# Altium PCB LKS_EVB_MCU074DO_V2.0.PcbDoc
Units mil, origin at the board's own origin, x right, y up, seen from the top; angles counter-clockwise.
Board outline 2625 x 1560 mil, 2 copper layers (Top Layer, Bottom Layer); 38 components, 55 nets, 182 pads, 64 vias.
Unrouted connection lines stored in the file: 4.
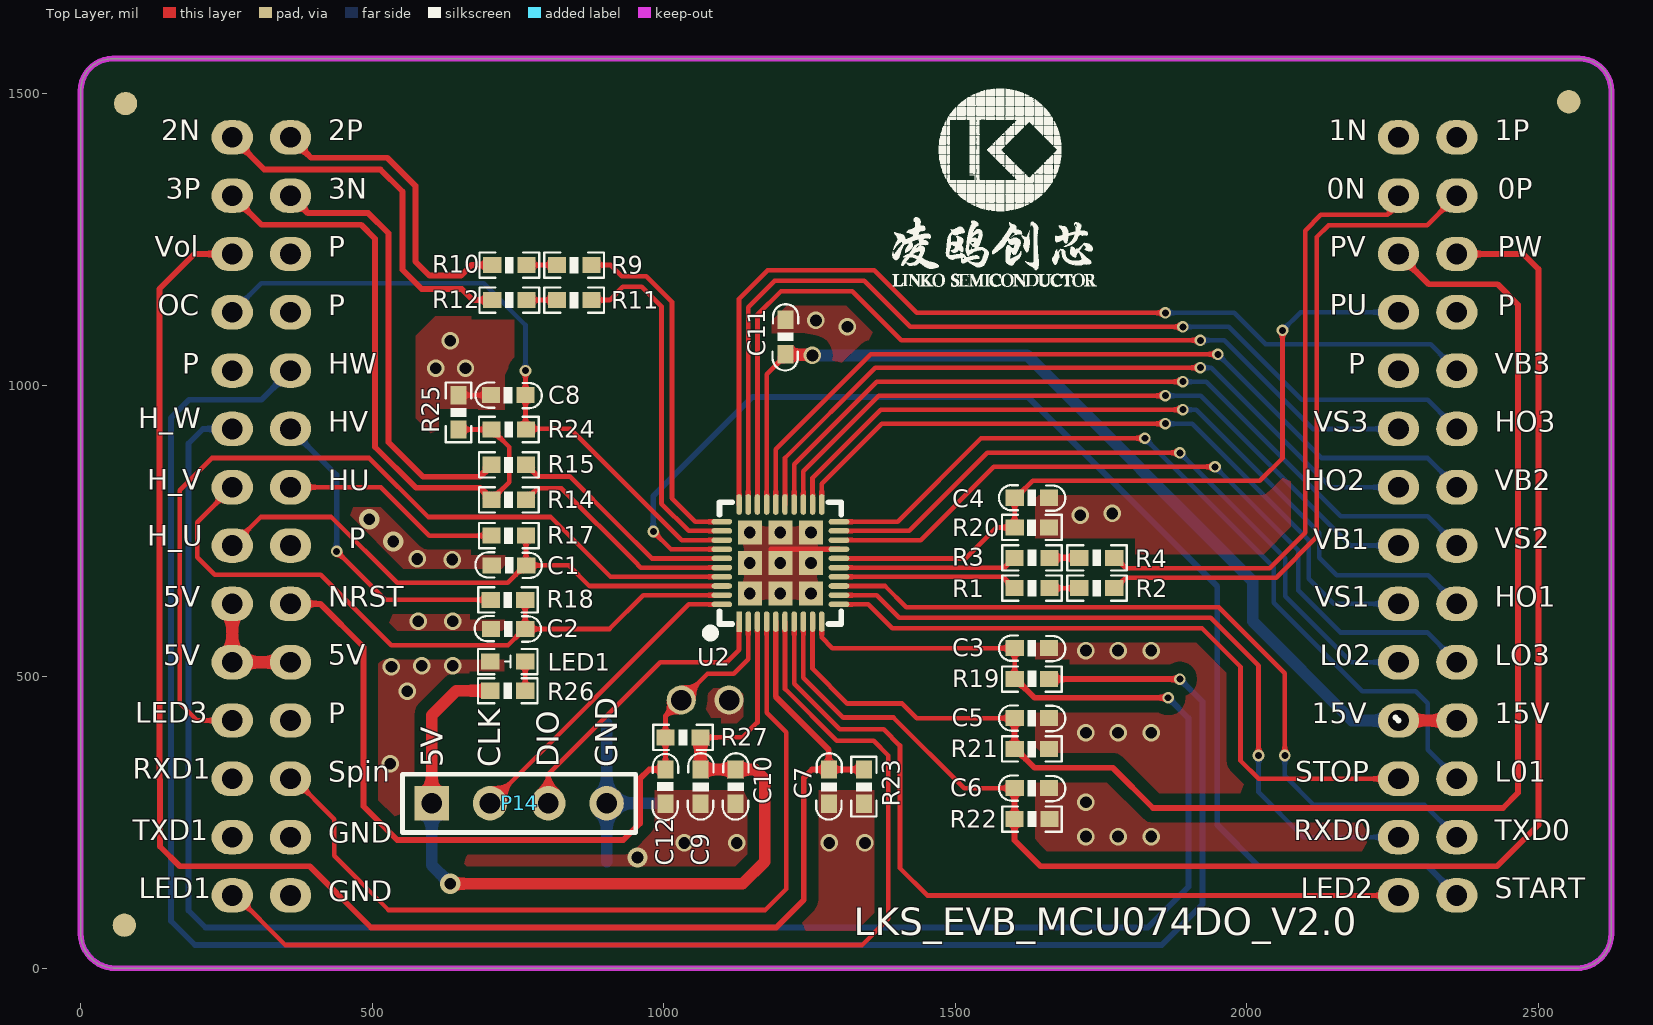
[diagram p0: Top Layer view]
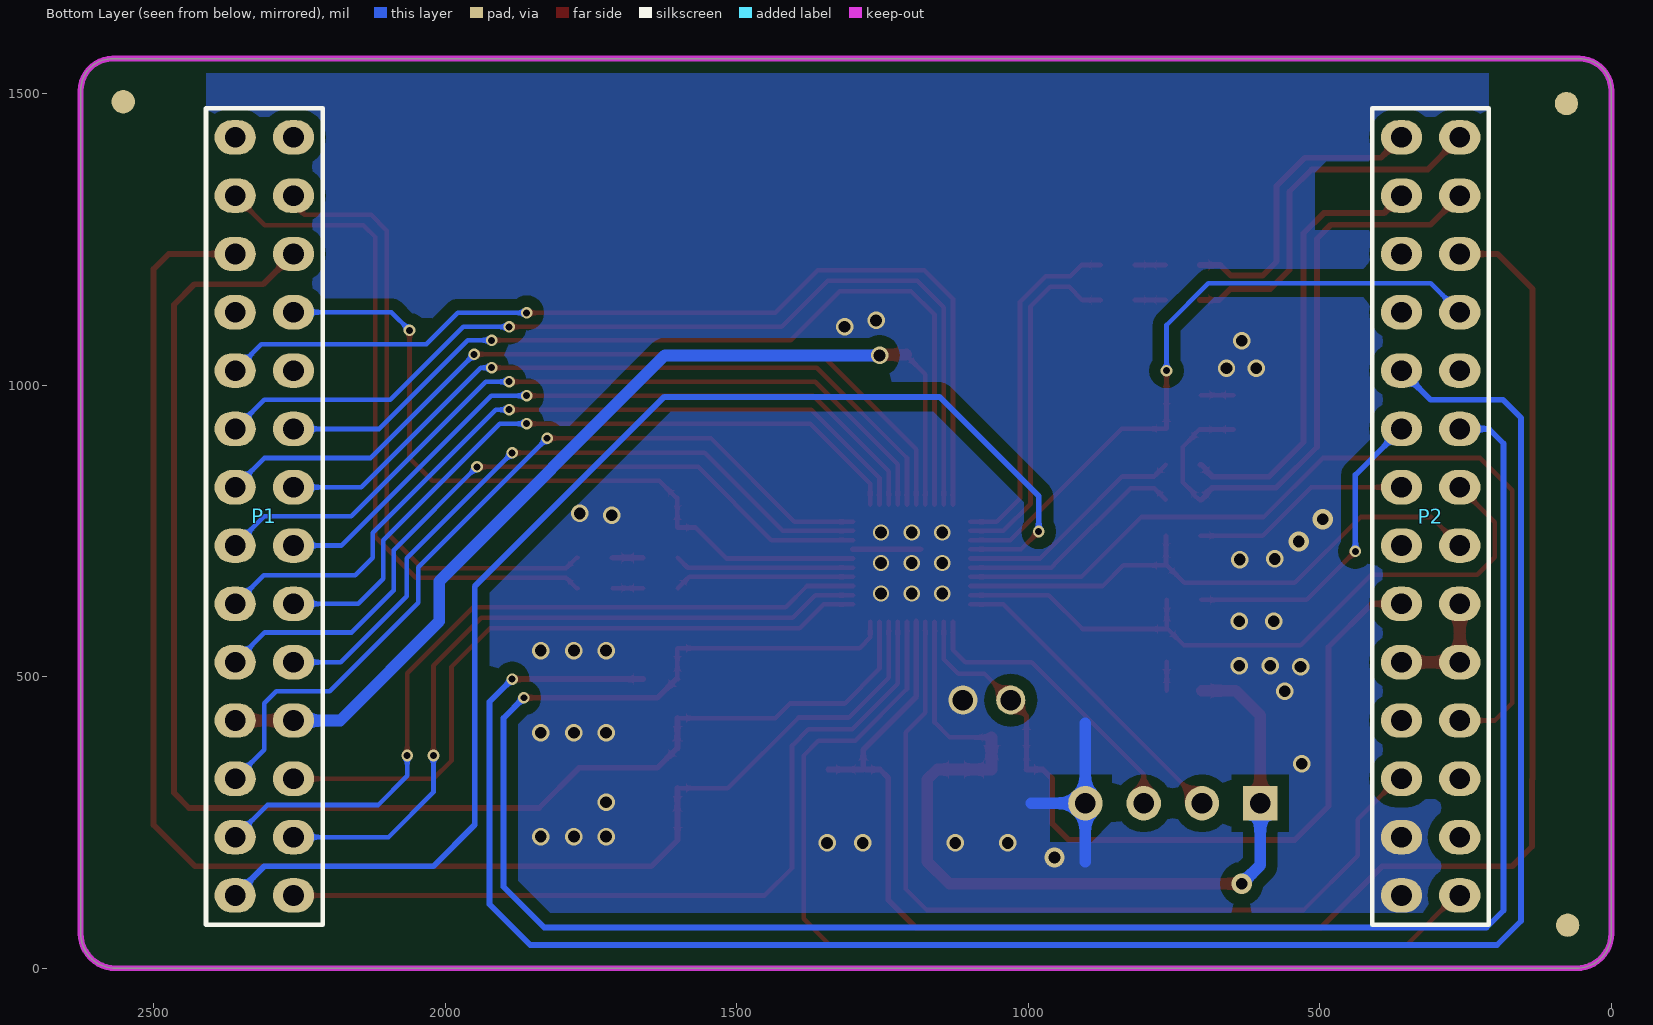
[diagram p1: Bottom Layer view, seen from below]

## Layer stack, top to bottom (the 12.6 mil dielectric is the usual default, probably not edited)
Top Solder: solder mask 0.4, Solder Resist, Dk 3.5
Top Layer: signal copper 1.4
Dielectric1: dielectric 12.6, FR-4, Dk 4.8
Bottom Layer: signal copper 1.4
Bottom Solder: solder mask 0.4, Solder Resist, Dk 3.5

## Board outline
0,60 ccw(c60,60) 60,0 2565,0 ccw(c2565,60) 2625,60 2625,1505 ccw(c2570,1505) 2570,1560 55,1560 ccw(c55,1505) 0,1505

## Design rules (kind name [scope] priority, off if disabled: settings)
Clearance Clearance_1 [InPolygon] p1: gap=20 ignorepadtopadclearanceinfootprint=FALSE except(0: Arc-Hole Track-Hole SMDPad-Hole THPad-Hole Via-Hole Fill-Hole Poly-Hole Region-Hole Text-Hole)
Clearance [All] p2: gap=0 ignorepadtopadclearanceinfootprint=FALSE
ComponentClearance [All] p1: gap=0 collisioncheckmode=3 verticalgap=0 showdistances=FALSE
FabricationTestpoint [(IsPad And (OnTopLayer Or OnBottomLayer))] p1: side=3 testpointundercomponent=TRUE minsize=40 maxsize=100 preferedsize=60 minholesize=0 maxholesize=40 preferedholesize=32 testpointgrid=1 allowsidetop=TRUE allowsidebottom=TRUE usegrid=TRUE gridtolerance=0.01
HoleSize [All] p1: absolutevalues=TRUE maxlimit=100 minlimit=0 maxpercent=80.000 minpercent=20.000
PolygonConnect [All] p1: connectstyle=Direct reliefconductorwidth=25 reliefentries=4 polygonreliefangle="90 Angle" airgapwidth=10
RoutingVias [All] p1: holewidth=28 width=50 viastyle="Through Hole" minholewidth=0 minwidth=8 maxholewidth=28 maxwidth=50
SilkToSolderMaskClearance SilkscreenOverComponentPads [IsPad] p1: minsilkscreentomaskgap=10 clearancetoexposedcopper=TRUE
SolderMaskExpansion [All] p1: expansion=4 istentingtop=FALSE
Width [All] p1: maxlimit=100 minlimit=2 preferedwidth=10
26 further rules are at their usual default settings.

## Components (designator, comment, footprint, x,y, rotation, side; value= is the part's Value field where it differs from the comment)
C1 "10nF/16V" 0603C 764.06,691 r180 top
C2 "10nF/16V" 0603C 762.71,581.86 r180 top
C3 "10nF/16V" 0603C 1601.65,549 r0 top
C4 "1nF/16V" 0603C 1601.65,807 r0 top
C5 "1nF/16V" 0603C 1601.65,429.21 r0 top
C6 "1nF/16V" 0603C 1601.65,309 r0 top
C7 "100nF/50V" 0603C 1283,281.94 r90 top
C8 "1nF/50V" 0603C 703.82,983 r0 top
C9 "10uF/16V" 0603C 1063,281.94 r90 top
C10 "100nF/50V" 0603C 1123,281.94 r90 top
C11 "4.7uF/25V" 0603C 1209,1112.23 r270 top
C12 "100nF/50V" 0603C 1003,341 r270 top
LED1 "LED" "LED 0603R" 732.5,526 r180 top
P1 "Header 14X2A" "HDR 2X14 底层" 2260,1425 r180 bottom
P2 "Header 14X2A" "HDR 2X14 底层" 260,1425 r180 bottom locked
P14 "Header 4" HDR1X4 602,283 r0 top
R1 "20K1%" 0603R#1 1631.36,652 r180 top value=K
R2 "20K1%" 0603R#1 1742.71,652 r180 top value=K
R3 "20K1%" 0603R#1 1631.36,704 r180 top value=K
R4 "20K1%" 0603R#1 1742.71,704 r180 top value=K
R9 "20K1%" 0603R#2 816.94,1206 r0 top value=K
R10 "20K1%" 0603R#2 705.65,1206 r0 top value=K
R11 "20K1%" 0603R#2 816.94,1146 r0 top value=K
R12 "20K1%" 0603R#2 705.65,1146 r0 top value=K
R14 "1K1%" 0603R#2 704.65,803.5 r0 top value=K
R15 "1K1%" 0603R#2 704.65,863.5 r0 top value=K
R17 "2K" 0603R#2 704.65,741.9 r0 top value=K
R18 "2K" 0603R#2 703.3,631.86 r0 top value=K
R19 "2K" 0603R#2 1660.71,496 r180 top value=K
R20 "1K" 0603R#2 1601.65,756 r0 top value=K
R21 "1K" 0603R#2 1601.65,376.21 r0 top value=K
R22 "1K" 0603R#1 1631.36,256 r0 top value=K
R23 "1K1%" 0603R#2 1343,282 r90 top value=K
R24 "1K1%" 0603R#2 763.71,924 r180 top value=K
R25 "10R" 0603R#2 648,923.94 r90 top value=K
R26 "330R" 0603R#1 732.5,476 r180 top value=330
R27 "20K" 0603R#1 1033,396 r0 top value=K
U2 "LKS32MC074DOF8Q8" QFN40 1200,695 r90 top

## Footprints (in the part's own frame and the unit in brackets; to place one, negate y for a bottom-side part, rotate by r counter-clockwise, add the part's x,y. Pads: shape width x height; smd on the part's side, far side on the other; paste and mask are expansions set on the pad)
0603C [mm]
  rect 0.8x0.7 smd: 1(0,0) 2(1.5,0)
  silkscreen extent -0.68,-0.57 2.21,0.55
0603R#1 [mm] "电阻"
  rect 0.8x0.7 smd: 1(-0.762,0) 2(0.762,0)
  silkscreen extent -1.3,-0.55 1.3,0.55, body extent -0.8,-0.4 0.8,0.4, height 0.45
0603R#2 [mm]
  rect 0.8x0.7 smd: 1(0,0) 2(1.5,0)
  silkscreen extent -0.55,-0.55 2.05,0.55
HDR1X4 [mm] "Connector; Header; 4 Position"
  rect 1.5x1.5 hole 0.9: 1(0,0)
  round 1.5 hole 0.9: 2(2.54,0) 3(5.08,0) 4(7.62,0)
  silkscreen extent -1.27,-1.27 8.89,1.27
"HDR 2X14 底层" [mm] "双排针 2.54mm 底层"
  oval 1.8x1.5 hole 0.9: 1(0,0) 2(0,-2.54) 3(0,-5.08) 4(0,-7.62) 5(0,-10.16) 6(0,-12.7) 7(0,-15.24) 8(0,-17.78) 9(0,-20.32) 10(0,-22.86) 11(0,-25.4) 12(0,-27.94) 13(0,-30.48) 14(0,-33.02) 15(-2.54,0) 16(-2.54,-2.54) 17(-2.54,-5.08) 18(-2.54,-7.62) 19(-2.54,-10.16) 20(-2.54,-12.7) 21(-2.54,-15.24) 22(-2.54,-17.78) 23(-2.54,-20.32) 24(-2.54,-22.86) 25(-2.54,-25.4) 26(-2.54,-27.94) 27(-2.54,-30.48) 28(-2.54,-33.02)
  silkscreen extent -3.81,-34.29 1.27,1.27, body extent -3.81,-34.29 1.27,1.27, height 8.5
"LED 0603R" [mm] "LED"
  rect 0.8x0.7 smd: 1(-0.762,0) 2(0.762,0)
  silkscreen extent -1.3,-0.55 1.3,0.55, body extent -0.8,-0.4 0.8,0.4, height 0.47
QFN40 [mm] "LINKO-084D"
  rect 1.05x1.05 smd: 0(-1.33,-1.33) 0(-1.33,0) 0(-1.33,1.33) 0(0,1.33) 0(0,0) 0(0,-1.33) 0(1.33,-1.33) 0(1.33,0) 0(1.33,1.33)
  rect 0.9x0.24 smd: 1(-2.55,1.8)
  oval 0.9x0.24 smd: 2(-2.55,1.4) 3(-2.55,1) 4(-2.55,0.6) 5(-2.55,0.2) 6(-2.55,-0.2) 7(-2.55,-0.6) 8(-2.55,-1) 9(-2.55,-1.4) 10(-2.55,-1.8) 21(2.55,-1.8) 22(2.55,-1.4) 23(2.55,-1) 24(2.55,-0.6) 25(2.55,-0.2) 26(2.55,0.2) 27(2.55,0.6) 28(2.55,1) 29(2.55,1.4) 30(2.55,1.8)
  oval 0.24x0.9 smd: 11(-1.8,-2.55) 12(-1.4,-2.55) 13(-1,-2.55) 14(-0.6,-2.55) 15(-0.2,-2.55) 16(0.2,-2.55) 17(0.6,-2.55) 18(1,-2.55) 19(1.4,-2.55) 20(1.8,-2.55) 31(1.8,2.55) 32(1.4,2.55) 33(1,2.55) 34(0.6,2.55) 35(0.2,2.55) 36(-0.2,2.55) 37(-0.6,2.55) 38(-1,2.55) 39(-1.4,2.55) 40(-1.8,2.55)
  silkscreen extent -3.16,-2.65 2.65,3.16, body extent -3,-3 3,3, height 0.9

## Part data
C1 C2 C3 C4 C5 C6: library part CAP, "Capacitor"
C7 C8 C9 C10 C11 C12: library part C, "Capacitor"
LED1: "LED_Light"
P1 P2: "Header, 14-Pin, Dual row"
P14: "Header, 4-Pin"
R1 R2 R3 R4 R9 R10 R11 R12 R14 R15 R17 R18 R19 R20 R21 R22 R23 R24 R25 R26 R27: library part Res, "Resistor"
U2: "凌鸥创芯，芯片，96M，64kK-Flash，12K-RAM,Built-in 6N Gate Drive+ldo5v"

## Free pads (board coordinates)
  round 50 hole 35: 0(1112,460) 1(1030,460)
  round 40 all layers, no hole: 3(2552,1486) 5(75,74) 5(77,1483)

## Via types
v1: diameter 30, hole 20, Top Layer to Bottom Layer, 31 vias
v2: diameter 20, hole 12, Top Layer to Bottom Layer, 20 vias
v3: diameter 28, hole 20, Top Layer to Bottom Layer, 9 vias
v4: diameter 35, hole 20, Top Layer to Bottom Layer, 4 vias

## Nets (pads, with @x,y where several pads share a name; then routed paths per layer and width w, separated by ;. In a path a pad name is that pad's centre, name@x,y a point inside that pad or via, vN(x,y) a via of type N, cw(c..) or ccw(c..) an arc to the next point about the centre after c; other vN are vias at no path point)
5V: P2.9 P2.10 P2.24 | length 200
  Top Layer w20: P2.9 P2.10 P2.24
+5V: C9.2 C10.2 P14.1 R26.2 R27.2 U2.3 | length 1569.1
  Top Layer w8: R27.2 1135,396 1160.63,421.63 U2.3
  Top Layer w20: P14.1 602,434 644,476 R26.2 ; v4(634.06,145) 1135,145 1173,183 1173,324 1156,341 C10.2 C9.2 R27.2
  Bottom Layer w20: P14.1 602,177.06 v4(634.06,145)
+15V: C11.2 P1.11 P1.25 U2.27 | length 1722.9
  Top Layer w8: U2.27 1176.38,1018.58 1209,1051.2 C11.2
  Top Layer w20: C11.2 1210.09,1052.09 1253.91,1052.09 v1(1255,1051) ; P1.11 P1.25
  Bottom Layer w20: v1(1255,1051) 1623,1051 2010,664 2010,595 2180,425 P1.11
GND: C1.2 C2.2 C3.2 C4.2 C5.2 C6.2 C7.1 C8.1 C9.1 C10.1 C11.1 C12.2 LED1.2 P2.16 P2.27 P2.28 P14.4 pad.0 R15.1 R20.2 R21.2 R22.2 R23.1 R25.2 U2.0 U2.17 | length 1265.5
  Top Layer w8: R25.2 C8.1
  Top Layer w10: P2.16 390,1295 493.28,1295 527.87,1260.4 527.87,902.13 587,843 684.39,843 693.91,852.51 693.91,854.72 702.69,863.5 R15.1@704.89,863.5 ; 1185,718.62 U2.17 ; U2.0@1200,695 v3(1200,695.11)
  Bottom Layer w20: 902,183 P14.4 ; 902,420 P14.4 ; 995,283 P14.4
  other v1: 1035,215 1125,215 1284,215 1345,215 1724,226 1779,226 1836,226 1724,285 531,351 1724,404 1779,404 1836,404 560,475 533,517 585,519 638,519 1724,545 1779,545 1836,545 579,595 638,595 637,701 577,702 1714,777 1769,780 609,1029 660,1029 634,1076 1315,1100 1261,1111
  other v3: 1147.64,642.64 1200,642.64 1252.36,642.64 1147.64,695 1252.36,695 1147.64,747.36 1200,747.36 1252.36,747.36
  other v4: 955,190 536,732 495,770
HALL_U: C1.1 P2.8 R17.2 U2.38 | length 984.8
  Top Layer w8: P2.8 309,774 430,774 543,661 732.09,661 762.09,691 C1.1 ; R17.2 763.71,691.35 C1.1 ; U2.38 872.37,655.63 837,691 C1.1
HALL_V: C2.1 P2.7 R18.2 U2.39 | length 1192.7
  Top Layer w8: P2.7 200,765 200,705 230,675 412,675 533,554 732.88,554 760.74,581.86 C2.1 ; R18.2 762.36,582.2 C2.1 ; U2.39 964.88,639.88 906.86,581.86 C2.1
HALL_W: C3.1 P2.6 R19.2 U2.10 | length 3676.5
  Top Layer w8: U2.10 1270.87,567.37 1289.24,549 C3.1 1601.65,497 R19.2@1600.65,496 ; R19.2 R19.2@1603.62,496
  Top Layer w10: R19.2@1603.62,496 1635.62,464 v2(1865,464)
  Bottom Layer w10: P2.6 210,925 185,900 185,99 214,70 1830,70 1900,140 1900,429 v2(1865,464)
HO1: P1.23 U2.22 | length 1362.1
  Top Layer w8: U2.22 1255.12,841.12 1372,958 v2(1890,958)
  Bottom Layer w8: v2(1890,958) 1913,958 2124,747 2124,704 2154,674 2311,674 P1.23
HO2: P1.7 U2.25 | length 1280.9
  Top Layer w8: U2.25 1207.87,875.1 1362.77,1030 v2(1920,1030)
  Bottom Layer w8: v2(1920,1030) 1939,1030 2144,825 P1.7
HO3: P1.20 U2.29 | length 1677.5
  Top Layer w8: U2.29 1144.88,1133.88 1190,1179 1344,1179 1423,1100 v2(1890,1100)
  Bottom Layer w8: v2(1890,1100) 1969,1100 2094,975 2310,975 P1.20
HU: P2.21 R17.1 | length 379.1
  Top Layer w8: P2.21 515,825 598.1,741.9 R17.1
HV: P2.20 R18.1 | length 541.5
  Top Layer w8: v2(439,715) 522.14,631.86 R18.1
  Bottom Layer w9.45: P2.20 439,846 v2(439,715)
HW: P2.19 R19.1 | length 3543
  Top Layer w10: R19.1 v2(1885,496)
  Bottom Layer w10: P2.19 310,975 186,975 155,944 155,81 196,40 1854,40 1924,110 1924,457 v2(1885,496)
LED1: P2.14 U2.6 | length 1798.7
  Top Layer w8: P2.14 265.91,125 350.91,40 1340,40 1385,85 1385,175 1385,365 1360,390 1297,390 1207.87,479.13 U2.6
LED2: P1.14 U2.7 | length 1416.1
  Top Layer w8: U2.7 1223.62,488.38 1302,410 1377,410 1405,382 1405,172 1452,125 P1.14
LED3: P2.11 U2.37 | length 1504.2
  Top Layer w8: P2.11 200,425 170,455 170,820 225,875 495.11,875 596.11,774 806,774 908.62,671.38 U2.37
LO1: P1.26 U2.20 | length 1443.1
  Top Layer w8: U2.20 1400.87,765.87 1544,909 v2(1825,909)
  Bottom Layer w8: v2(1825,909) 2046,688 2046,627 2198,475 2289.5,475 2310,454.5 2310,375 P1.26
LO2: P1.10 U2.19 | length 1201.8
  Top Layer w8: U2.19 1421.12,750.12 1555,884 v2(1885,884)
  Bottom Layer w8: v2(1885,884) 2066,703 2066,638 2179,525 P1.10
LO3: P1.24 U2.18 | length 1291
  Top Layer w8: U2.18 1440.37,734.37 1566,860 v2(1945.31,860)
  Bottom Layer w8: v2(1945.31,860) 2088,717.31 2088,648 2160,576 2309,576 P1.24
NetLED1_1: LED1.1 R26.1 | length 50
  Top Layer w8: R26.1 LED1.1
NetR1_1: R1.1 R2.2 | length 52
  Top Layer w8: R1.1@1660.71,652 R2.2
NetR3_1: R3.1 R4.2 | length 51.7
  Top Layer w10: R3.1@1661,704 R4.2
NetR9_1: R9.1 R10.2 | length 52.2
  Top Layer w8: R10.2 R9.1
NetR11_1: R11.1 R12.2 | length 52.2
  Top Layer w8: R12.2 R11.1
NRST: C12.1 P2.23 pad.1 R27.1 U2.2 | length 1404.3
  Top Layer w8: C12.1 R27.1 1003,433 pad.1 1075,505 1120,505 1144.88,529.88 U2.2
  Top Layer w10: P2.23 411,625 485,551 485,278 543,220 930.5,220 959,248.5 959,325 975,341 C12.1
OC: C8.2 P2.4 R24.1 U2.33 | length 1147.1
  Top Layer w8: v2(762.87,1024.87) C8.2 762.87,925.18 839.82,925.18 1030.63,734.37 U2.33
  Bottom Layer w8: P2.4 310,1175 691,1175 762.87,1103.13 v2(762.87,1024.87)
OPA0_IN: R3.2 U2.15 | length 307.6
  Top Layer w8: U2.15 1584.13,687.13 R3.2@1601,704
OPA0_IP: R1.2 U2.14 | length 308.3
  Top Layer w8: U2.14 1581.33,671.38 R1.2@1600.71,652
OPA2_IN: R11.2 U2.32 | length 605.6
  Top Layer w8: R11.2@876.65,1145.35 R11.2 907,1146 930,1169 962,1169 996,1135 996,797 1042.88,750.12 U2.32
OPA2_IP: R9.2 U2.31 | length 603.3
  Top Layer w8: R9.2 909,1206 928,1187 970,1187 1014,1143 1014,806 1054.13,765.87 U2.31
OPA3_IN: R15.2 U2.35 | length 402.2
  Top Layer w8: R15.2@763.95,863.5 783.95,843.5 838.5,843.5 920,762 979.13,702.87 U2.35
OPA3_IP: R14.2 U2.36 | length 400.4
  Top Layer w8: R14.2@763.95,803.5 783.95,823.5 824.5,823.5 950,698 960.87,687.13 U2.36
PGND: P1.1 P1.2 P2.1 P2.2 R4.1 R12.1 R14.1 R24.2 R25.1 | length 2786.8
  Top Layer w8: R25.1 704.94,923.94 705,924 706.97,924 716.75,914.22 716.75,912.25 735,894 735,833.61 716.64,815.25 716.64,813.28 706.86,803.5 R14.1@704.89,803.5 ; R4.1 1774.68,704 1792.68,686 2039,686 2100,747 2100,1265 2127,1292 2241,1292 2260,1311 P1.2
  Top Layer w10: P2.2 310,1275 481,1275 505,1251 505,894 575,824 684.39,824 693.91,814.49 693.91,812.28 702.69,803.5 R14.1@704.89,803.5 ; P2.1 315,1370 514,1370 552,1332 552,1198 585,1165 653.55,1165 672.55,1146 R12.1
PU: C4.1 P1.4 R20.1 U2.16 | length 1292.6
  Top Layer w8: U2.16 1517.87,702.87 1571,756 R20.1 C4.1 1603.62,807 1632.62,836 2022,836 2061,875 v2(2061,1094)
  Bottom Layer w8: v2(2061,1094) 2092,1125 P1.4
PV: C5.1 P1.3 R21.1 U2.9 | length 2508.8
  Top Layer w8: U2.9 1255.12,513.88 1315,454 1409.05,454 1434.05,429 1601.44,429 C5.1 ; R21.1 R21.1@1603.62,376.21
  Top Layer w10: R21.1@1601.65,377 C5.1 ; R21.1@1603.62,376.21 1635.84,344 1770,344 1839,275 2439,275 2465,301 2465,1138 2430,1173 2312,1173 P1.3
PW: C6.1 P1.17 R22.1 U2.8 | length 2676.6
  Top Layer w8: U2.8 1239.37,498.63 1308,430 1394,430 1515,309 C6.1
  Top Layer w10: C6.1 1601.65,256.29 R22.1 1601.36,219.64 1646,175 2429,175 2500,246 2500,1199 2474,1225 P1.17
RXD0: P1.13 U2.12 | length 1258.6
  Top Layer w8: U2.12 1365.12,639.88 1404,601 1938,601 2020,519 v2(2020,365)
  Bottom Layer w8: v2(2020,365) 2020,302 2097,225 P1.13
RXD1: P2.12
SPIN: P2.26 U2.4 | length 1467.5
  Top Layer w8: P2.26 365.91,325 435,255.91 435,193 528,100 1174,100 1210,136 1210,405 1176.38,438.62 U2.4
START1: P1.28 U2.34 | length 2233.3
  Top Layer w8: v2(982,749) 1012.38,718.62 U2.34
  Bottom Layer w10: v2(982,749) 982,810 1152,980 1624,980 1949,655 1949,246 2020,175 2310,175 P1.28
STOP1: P1.12 U2.11 | length 1177.8
  Top Layer w8: U2.11 1350.87,624.13 1392,583 1923,583 1989,517 1989,356 2020,325 P1.12
SWCLK: P14.2 U2.40 | length 538.9
  Top Layer w8: P14.2 1043.13,624.13 U2.40
SWDIO: P14.3 U2.1 | length 513.9
  Top Layer w8: P14.3 802,333 994,525 1108,525 1129.13,546.13 U2.1
TXD0: P1.27 U2.13 | length 1341.1
  Top Layer w8: U2.13 1379.37,655.63 1416,619 1952,619 2065,506 v2(2065,365)
  Bottom Layer w8: v2(2065,365) 2065,330 2115,280 2305,280 P1.27
TXD1: P2.13
UP-: P2.15 R10.1 | length 527.4
  Top Layer w10: P2.15 395,1390 526,1390 574,1342 574,1212 598,1188 652.52,1188 670.52,1206 R10.1
VB1: P1.8 U2.23 | length 1237.8
  Top Layer w8: U2.23 1239.37,852.37 1369,982 v2(1860,982)
  Bottom Layer w8: v2(1860,982) 1921,982 2178,725 P1.8
VB2: P1.21 U2.26 | length 1424.5
  Top Layer w8: U2.26 1192.13,890.13 1355,1053 v2(1950,1053)
  Bottom Layer w8: v2(1950,1053) 2128,875 2310,875 P1.21
VB3: P1.19 U2.30 | length 1675.1
  Top Layer w8: U2.30 1129.13,1148.13 1178,1197 1361,1197 1434,1124 v2(1860,1124)
  Bottom Layer w8: v2(1860,1124) 1978,1124 2032,1070 2315,1070 P1.19
VOL_ADC: C7.2 P2.3 R23.2 U2.5 | length 2892.4
  Top Layer w10: P2.3 195,1225 135,1165 135,325 136,324 136,209 170,175 393,175 498,70 1193,70 1240,117 1240,327 1254,341 C7.2@1278,341 ; U2.5 1192.13,465.87 1283,375 C7.2 1342.94,341 R23.2
VP-: P1.15
VS1: P1.9 U2.21 | length 1234
  Top Layer w8: U2.21 1270.87,830.87 1374,934 v2(1860,934)
  Bottom Layer w8: v2(1860,934) 1906,934 2106.13,733.87 2106.13,667.87 2149,625 P1.9
VS2: P1.22 U2.24 | length 1380.6
  Top Layer w8: U2.24 1223.62,864.62 1365,1006 v2(1890,1006)
  Bottom Layer w8: v2(1890,1006) 1930,1006 2161,775 2310,775 P1.22
VS3: P1.6 U2.28 | length 1539.1
  Top Layer w8: U2.28 1160.63,1120.63 1201,1161 1323,1161 1407,1077 v2(1920.25,1077)
  Bottom Layer w8: v2(1920.25,1077) 1961,1077 2113,925 P1.6
WP-: P1.16 R2.1 | length 1167.2
  Top Layer w8: R2.1 1774.68,652 1792.68,670 2050,670 2120,740 2120,1254.13 2140,1274.13 2309.13,1274.13 P1.16
pads on no net: P1.5 P1.18 P2.5 P2.17 P2.18 P2.22 P2.25

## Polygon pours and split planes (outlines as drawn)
GND on Bottom Layer "Bottom Layer-No Net 1" (solid, remove dead copper, pour order 9): 210,1560 2410,1560 2410,-2 210,-2
GND on Top Layer "Bottom Layer-No Net 1" (solid, remove dead copper, pour order 5): 210,1560 210,0 2410,0 2410,1560

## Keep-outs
Keep-Out Layer:
  the board outline again, w10

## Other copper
Top Layer:
  pour cut-out: 300,1364 300,810 319.6,790.4 740.15,790.4 740.15,895 623,895 575,943 575,1085 608.4,1118.4 743.6,1118.4 743.6,1029.4 845.6,1029.4 845.6,1262.4 744,1364
  pour cut-out: 306,137 306,5 297,5 289,5 289,100
  pour cut-out: 298.86,275 296,5 436,5 445,5 445,275
  pour cut-out: 855,382 855,253 892,216 893,217 963,217 963,381 962,382 961,381 856,381
Bottom Layer:
  pour cut-out: 856,333 856,254 855,253 891.5,216.5 962.5,216.5 963,217 963,333
  pour cut-out: 303,1384 489,1384 509,1364 509,1266 313,1266 304,1275

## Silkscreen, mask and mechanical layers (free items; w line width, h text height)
Top Overlay:
  drawing of 145 lines, arcs and shapes, not listed
  text "2N" at 138,1408 h60
  text "2P" at 425,1408 h60
  text "1N" at 2140,1408 h60
  text "1P" at 2425,1408 h60
  text "3P" at 146,1308 h60
  text "3N" at 425,1308 h60
  text "0N" at 2137,1308 h60
  text "0P" at 2430,1308 h60
  text "Vol" at 127,1208 h60
  text "P" at 425,1208 h60
  text "PV" at 2142,1208 h60
  text "PW" at 2430,1208 h60
  text "PU" at 2142,1109 h60
  text "OC" at 132,1108 h60
  text "P" at 425,1108 h60
  text "P" at 2430,1108 h60
  text "P" at 174,1008 h60
  text "HW" at 425,1008 h60
  text "P" at 2174,1008 h60
  text "VB3" at 2425,1008 h60
  text "H_W" at 99,914 h60
  text "HV" at 425,908 h60
  text "VS3" at 2115,908 h60
  text "HO3" at 2425,908 h60
  text "H_V" at 114,809 h60
  text "HU" at 425,808 h60
  text "HO2" at 2098,808 h60
  text "VB2" at 2425,808 h60
  text "H_U" at 114,713 h60
  text "P" at 460,708 h60
  text "VS2" at 2425,708 h60
  text "VB1" at 2114,707 h60
  text "5V" at 142,608 h60
  text "NRST" at 425,608 h60
  text "VS1" at 2116,608 h60
  text "HO1" at 2425,608 h60
  text "5V" at 425,509 h60
  text "5V" at 142,508 h60
  text "L02" at 2125,508 h60
  text "LO3" at 2425,508 h60
  text "LED3" at 94,409 h60
  text "P" at 425,408 h60
  text "15V" at 2111,408 h60
  text "15V" at 2425,408 h60
  text "5V" at 621,345 h38 r90
  text "CLK" at 720,345 h38 r90
  text "DIO" at 820,345 h38 r90
  text "GND" at 920,345 h38 r90
  text "RXD1" at 89,313 h60
  text "Spin" at 425,308 h60
  text "STOP" at 2083,308 h60
  text "L01" at 2425,308 h60
  text "TXD1" at 89,208 h60
  text "RXD0" at 2080,208 h60
  text "TXD0" at 2425,208 h60
  text "GND" at 425,203 h60
  text "LED1" at 100,108 h60
  text "LED2" at 2092,108 h60
  text "START" at 2425,108 h60
  text "GND" at 425,103 h60
  text "LKS_EVB_MCU074DO_V2.0" at 1326,41 h80
Top Solder:
  circle w78: c75,74 r17
  circle w78: c2552,1486 r17
  circle w78: c77,1483 r17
